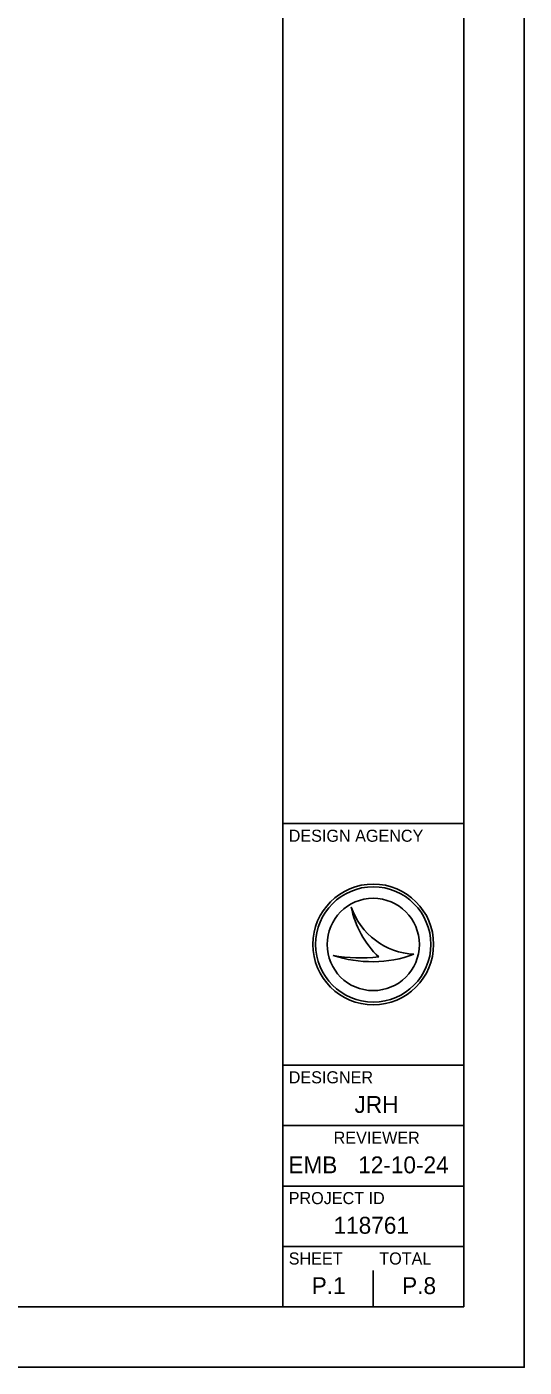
# Model space of a CAD drawing. Extents: x 0 to 34, y 0 to 22.
# Drawn here: x 29.88 to 34, y 0 to 11.1 of the extents above; entities that cross this region are included whole.
import ezdxf

# ---------------------------------------------------------------- set-up
doc = ezdxf.new("R2010")
doc.units = 0
for name, color, linetype in [('SH_Border', 7, 'Continuous'), ('SH_Cut_Line', 7, 'Continuous'), ('SH_Data', 7, 'Continuous')]:
    doc.layers.add(name, color=color, linetype=linetype)

msp = doc.modelspace()

# ---------------------------------------------------------------- linework, layer by layer
at = {"layer": 'SH_Border'}
for p, q in [((32, 0.5), (32, 21.5)), ((32, 4.5), (33.5, 4.5)), ((32, 2.5), (33.5, 2.5)), ((32, 2), (33.5, 2)), ((32, 1.5), (33.5, 1.5)), ((32, 1), (33.5, 1))]:
    msp.add_line(p, q, dxfattribs=at)
msp.add_lwpolyline([(1.5, 21.5), (33.5, 21.5), (33.5, 0.5), (1.5, 0.5)], close=True, dxfattribs=at)
at = {"layer": 'SH_Cut_Line'}
msp.add_lwpolyline([(0, 0), (34, 0), (34, 22), (0, 22)], close=True, dxfattribs=at)
at = {"layer": 'SH_Data'}
for p, q in [((32.567, 3.81), (32.567, 3.81)), ((32.75, 3.5), (32.75, 3.5)), ((32.417, 3.41), (32.417, 3.41)), ((33.087, 3.419), (33.087, 3.419)), ((32.75, 0.5), (32.75, 0.8)), ((32.375, 0.675), (32.375, 0.675))]:
    msp.add_line(p, q, dxfattribs=at)
for radius in [0.5, 0.477, 0.477, 0.382]:
    msp.add_circle((32.75, 3.5), radius, dxfattribs=at)
for centre, radius, start, end in [((33.116, 3.998), 0.58, 198.9257, 198.9319), ((33.347, 3.97), 0.796, 191.6379, 191.6421), ((33.116, 3.998), 0.58, 198.9319, 267.1657), ((33.347, 3.97), 0.796, 191.6421, 226.0947), ((32.739, 4.37), 1.013, 251.4576, 290.0832), ((32.648, 4.654), 1.266, 259.4964, 259.4995), ((32.739, 4.37), 1.013, 251.4527, 251.4576), ((32.648, 4.654), 1.266, 259.4995, 276.6672)]:
    msp.add_arc(centre, radius, start, end, dxfattribs=at)

# ---------------------------------------------------------------- texts
for s, height, p in [('DESIGN AGENCY', 0.1, (32.05, 4.35)), ('DESIGNER', 0.1, (32.05, 2.35)), ('JRH', 0.14, (32.595, 2.105)), ('REVIEWER', 0.1, (32.422, 1.85)), ('EMB', 0.14, (32.047, 1.605)), ('12-10-24', 0.14, (32.625, 1.605)), ('PROJECT ID', 0.1, (32.05, 1.35)), ('118761', 0.14, (32.421, 1.105)), ('SHEET', 0.1, (32.05, 0.85)), ('TOTAL', 0.1, (32.8, 0.85)), ('P.1', 0.14, (32.24, 0.605)), ('P.8', 0.14, (32.989, 0.605))]:
    msp.add_text(s, height=height, dxfattribs=at).set_placement(p)

doc.saveas('drawing.dxf')
